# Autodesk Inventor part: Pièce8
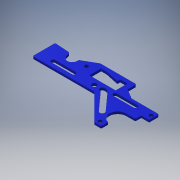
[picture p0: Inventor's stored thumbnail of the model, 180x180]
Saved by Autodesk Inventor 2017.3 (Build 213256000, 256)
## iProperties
Created: 2007-11
Part Number: Pièce8
Material: Générique
Document SubType Name: Modeling
Designer: ficho
Density: 1 g/cm^3
Appearance: Bleu - Peinture murale - Brillant
Author: ficho
Sending System: SolidWorks 2009
Last Author: christophe
Last Saved: 2011-01-19
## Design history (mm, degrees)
feature "Congé2"
node "Solide1"
